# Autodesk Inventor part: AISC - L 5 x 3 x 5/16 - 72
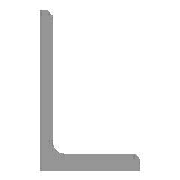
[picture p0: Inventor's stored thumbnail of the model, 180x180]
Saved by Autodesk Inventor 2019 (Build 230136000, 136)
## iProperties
Created: 2019-01
Part Number: AISC - L 5 x 3 x 5/16 - 72
Material: Steel, Mild
Description: Angle Steel
Document SubType Name: Modeling
Standard: ANSI
Designer: ElizabethC
Standards Organization: ANSI
Language: en-US
Size Designation: L 5 x 3 x 5/16
Categories: <MemberInstance><Categories><Category DisplayName="Structural Shapes" InternalName="089c4875-fa83-4c05-b084-43b9cc11f5ed" Mnemonic="GRDR"><CategoryParameter Dis
Stock Number: L 5 x 3 x 5/16
Mass: 21446.1 g
Surface Area: 6954.6 cm^2
Volume: 2731.98 cm^3
Density: 7.85 g/cm^3
Appearance: Semi-Polished
IsCustomPart: 1
_CCFamilyMember: 39
_CCFamilyDisplayName: ANSI L (Unequal angles) - Angle Steel — Sizes in parentheses have been withdrawn
_FrameMemberDoc: Frame Member File
_Version: 15.0.0
_GetPNFromCC: 1
Author: ElizabethC
G_L: 72.000 in
G_W: 3.000 in
G_H: 5.000 in
+E36162CD-4C8B-4080-B5B9-4A733B6C026D+CUTDETAIL1: Miter 45.00 deg
+E242FEE0-D0F7-4038-91EE-160DF7B02C19+CUTDETAIL2: Miter 45.00 deg
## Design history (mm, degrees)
node "Start plane"
node "End plane"
sketch "Sketch"
  geometry: L1 (70.612, 7.95)-(19.126, 7.95); L2 (0, 0)-(76.2, 0); L3 (76.2, 0)-(76.2, 2.362); L4 (-7.041, 0)-(21.538, 0); L5 (7.95, 19.126)-(7.95, 121.412); L6 (0, 127)-(0, 0); L7 (2.362, 127)-(0, 127); L8 (0, -8.041)-(0, 34.538); L9 (0, 155.397)-(0, -35.281) reference; L10 (-23.921, 0)-(94.237, 0) reference; A1 r 11.176 centre (19.126, 19.126) between (7.95, 19.126) and (19.126, 7.95); A2 r 5.588 centre (70.612, 2.362) between (76.2, 2.362) and (70.612, 7.95); A3 r 5.588 centre (2.362, 121.412) between (7.95, 121.412) and (2.362, 127); 3 further points
  constraints: 16 end point, 6 point on circle, 6 point on line, 6 tangent, 3 centre point, 2 collinear, 2 parallel, 1 equal radius
  dimensions: "d12" = 7.9502 distance between parallel lines of L5 L6 (= G_T); "d13" = 127 distance of L6.start L2.start (= G_H); "d14" = 76.2 distance of L2.start L2.end (= G_W); "d15" = 0 distance between parallel lines of L4 L2 (computed from ex); "d16" = 7.9502 distance between parallel lines of L2 L1 (= G_T); "d17" = 0 distance between parallel lines of L8 L6 (computed from ey); "d18" = 11.176 radius of A1 (= G_IR); "d19" = 5.588 radius of A2 (= G_ER)
extrude "Body" new body sketch "Sketch" stored distance "d4" = 1828.8 (= G_L); taper "d5" = 0 deg
node "Driven Length"
  sketch "Sketch3"
    geometry: L1 (0, 0)-(10, 0) reference
    constraints: 2 end point, 1 horizontal
  workplane "Work Plane3"
  sketch "Sketch4"
    geometry: L1 (-2, 0)-(12, 0) reference; L2 (-2, 1828.8)-(12, 1828.8) reference
    dimensions: "d23" = 1828.8 distance between parallel lines of L1 L2 (derived)
workplane "Work Plane4"
split "Split1"
workplane "Work Plane5"
split "Split2"
body "Solid1"
other parameters: "G_W" = 76.2 [user parameter; used in 1 equation term], "G_H" = 127 [user parameter; used in 1 equation term], "G_T" = 7.9502 [user parameter; used in 2 equation terms], "G_ER" = 5.588 [user parameter; used in 1 equation term], "G_IR" = 11.176 [user parameter; used in 1 equation term], "G_L" = 1828.8 (= d23) [user parameter; used in 1 equation term], "ex" = 0 [user parameter; used in 1 equation term], "ey" = 0 [user parameter; used in 1 equation term], "G_OFFSET_START" = 0 [user parameter; used in 1 equation term], "G_OFFSET_END" = 0 [user parameter; used in 1 equation term], "d20" = 0 (computed from G_OFFSET_START), "d21" = 1828.8 (= G_OFFSET_END + B_L), "B_L" = 1828.8 [user parameter; used in 1 equation term], "d22" = 90 deg, "MAS" = 1.22029 [user parameter]
